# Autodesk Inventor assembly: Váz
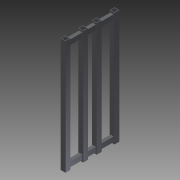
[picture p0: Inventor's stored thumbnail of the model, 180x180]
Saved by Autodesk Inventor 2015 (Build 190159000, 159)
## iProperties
Created: 2013-02
Part Number: Váz
Document SubType Name: Assembly
Designer: Marci
Author: Marci
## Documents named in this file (4)
- C:\Users\Andrew Almeida\Documents\Projeto WS2015\WS2015 CAD Data ANLAS\01\Pneumatic System\Engine\Pneumatikus hajtás\Váz.iam
- C:\Users\Andrew Almeida\Documents\Projeto WS2015\WS2015 CAD Data ANLAS\01\Pneumatic System\Engine\Pneumatikus hajtás\Vázelem.ipt
- C:\Users\Andrew Almeida\Documents\Projeto WS2015\WS2015 CAD Data ANLAS\01\Pneumatic System\Engine\Pneumatikus hajtás\Vázelem 53.ipt
- C:\Users\Andrew Almeida\Documents\Projeto WS2015\WS2015 CAD Data ANLAS\01\Pneumatic System\Engine\Pneumatikus hajtás\Vázelem 81.ipt
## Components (10 placed, 3 different names)
1. Vázelem:1 — Flush:1, Flush:2, Mate:1, Mate:4, Flush:7, Flush:8, Mate:9, Flush:17, Flush:18
2. Vázelem:2 — Flush:1, Flush:2, Mate:1, Flush:3, Flush:4, Mate:2, Mate:5, Flush:9, Flush:10, Mate:8, Flush:15, Flush:16
3. Vázelem:3 — Flush:3, Flush:4, Mate:2, Flush:5, Flush:6, Mate:3, Mate:6, Flush:11, Flush:12, Mate:7, Flush:13
4. Vázelem:4 — Flush:5, Flush:6, Mate:3, Flush:14
5. Vázelem 53:1 — Mate:5, Flush:9, Flush:10
6. Vázelem 81:1 — Mate:4, Flush:7, Flush:8
7. Vázelem 81:2 — Mate:6, Flush:11, Flush:12
8. Vázelem 81:3 — Mate:7, Flush:13, Flush:14
9. Vázelem 81:4 — Mate:9, Flush:17, Flush:18
10. Vázelem 53:2 — Mate:8, Flush:15, Flush:16
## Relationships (27: Flush 18, Mate 9)
- Flush:1: Vázelem:1 ↔ Vázelem:2
- Flush:2: Vázelem:1 ↔ Vázelem:2
- Mate:1: Vázelem:1 ↔ Vázelem:2
- Flush:3: Vázelem:2 ↔ Vázelem:3
- Flush:4: Vázelem:2 ↔ Vázelem:3
- Mate:2: Vázelem:2 ↔ Vázelem:3
- Flush:5: Vázelem:3 ↔ Vázelem:4
- Flush:6: Vázelem:3 ↔ Vázelem:4
- Mate:3: Vázelem:3 ↔ Vázelem:4
- Mate:4: Vázelem:1 ↔ Vázelem 81:1
- Flush:7: Vázelem:1 ↔ Vázelem 81:1
- Flush:8: Vázelem:1 ↔ Vázelem 81:1
- Mate:5: Vázelem:2 ↔ Vázelem 53:1
- Flush:9: Vázelem:2 ↔ Vázelem 53:1
- Flush:10: Vázelem:2 ↔ Vázelem 53:1
- Mate:6: Vázelem:3 ↔ Vázelem 81:2
- Flush:11: Vázelem:3 ↔ Vázelem 81:2
- Flush:12: Vázelem:3 ↔ Vázelem 81:2
- Mate:7: Vázelem:3 ↔ Vázelem 81:3
- Flush:13: Vázelem:3 ↔ Vázelem 81:3
- Flush:14: Vázelem:4 ↔ Vázelem 81:3
- Mate:8: Vázelem:2 ↔ Vázelem 53:2
- Flush:15: Vázelem:2 ↔ Vázelem 53:2
- Flush:16: Vázelem:2 ↔ Vázelem 53:2
- Mate:9: Vázelem:1 ↔ Vázelem 81:4
- Flush:17: Vázelem:1 ↔ Vázelem 81:4
- Flush:18: Vázelem:1 ↔ Vázelem 81:4
